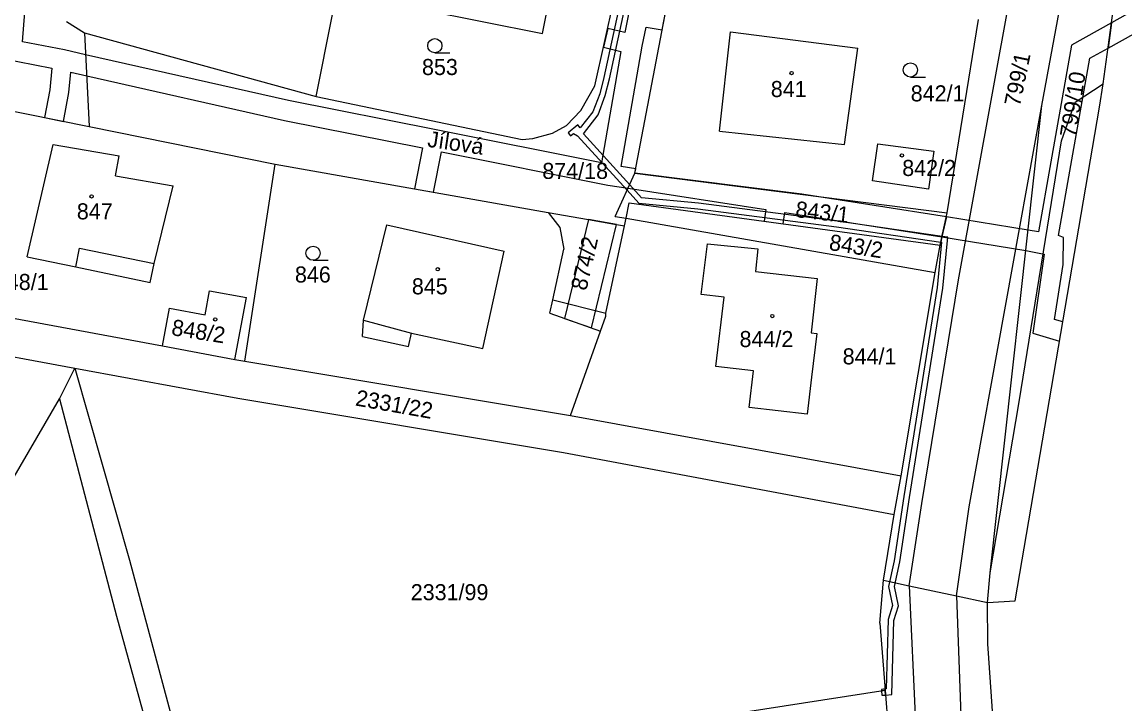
# Model space of a CAD drawing. Extents: x -785744 to -782822, y -1067550 to -1063910.
# Drawn here: x -783511.1 to -783394.4, y -1066451.8 to -1066379.6 of the extents above; entities that cross this region are included whole.
import ezdxf

# ---------------------------------------------------------------- set-up
doc = ezdxf.new("R2010")
doc.units = 0
for name, color, linetype in [('Hranice kat_území', 7, 'Continuous'), ('Hranice parcel', 7, 'Continuous'), ('Parcelní čísla', 7, 'Continuous'), ('Pop_ČP_popisy', 7, 'Continuous'), ('Vnitřní kresba', 7, 'Continuous'), ('Věcná břemena k části', 7, 'Continuous'), ('Značky budov', 7, 'Continuous'), ('Značky kultur', 7, 'Continuous')]:
    doc.layers.add(name, color=color, linetype=linetype)

msp = doc.modelspace()

# ---------------------------------------------------------------- linework, layer by layer
at = {"layer": 'Hranice kat_území'}
msp.add_lwpolyline([(-783403.72, -1066520.48), (-783408.95, -1066445.43), (-783408.98, -1066441.05), (-783406.06, -1066440.89), (-783397.12, -1066388.66), (-783396.74, -1066386.18), (-783395.27, -1066375.27), (-783394.46, -1066371.28), (-783389.04, -1066341.47), (-783386.35, -1066325.72), (-783383.12, -1066306.7), (-783381.34, -1066290.13), (-783381.25, -1066273.33), (-783383.32, -1066256.79), (-783387.23, -1066240.6), (-783392.79, -1066224.78), (-783395.02, -1066219.44), (-783397.61, -1066215.1), (-783400.51, -1066209.79), (-783408.68, -1066195.43), (-783410.8, -1066191.77), (-783425.61, -1066169.96)], dxfattribs=at)
at = {"layer": 'Hranice parcel'}
for p, q in [((-783421.15, -1066396.44), (-783420.59, -1066392.53)), ((-783420.59, -1066392.53), (-783414.67, -1066393.3)), ((-783414.67, -1066393.3), (-783415.23, -1066397.32)), ((-783415.23, -1066397.32), (-783421.15, -1066396.44)), ((-783439.26, -1066408.46), (-783438.61, -1066403.11)), ((-783438.61, -1066403.11), (-783433.28, -1066403.63)), ((-783433.28, -1066403.63), (-783433.51, -1066406.05)), ((-783433.51, -1066406.05), (-783426.98, -1066406.79)), ((-783426.98, -1066406.79), (-783427.64, -1066412.53)), ((-783436.84, -1066408.75), (-783439.26, -1066408.46)), ((-783437.72, -1066416.08), (-783436.84, -1066408.75)), ((-783427.64, -1066412.53), (-783427.04, -1066412.6)), ((-783427.04, -1066412.6), (-783427.6, -1066417.21)), ((-783433.72, -1066416.53), (-783437.72, -1066416.08)), ((-783434.18, -1066420.43), (-783433.72, -1066416.53)), ((-783427.6, -1066417.21), (-783428.07, -1066421.14)), ((-783428.07, -1066421.14), (-783434.18, -1066420.43)), ((-783419.8, -1066450.34), (-783417.13, -1066483.64))]:
    msp.add_line(p, q, dxfattribs=at)
for points in [[(-783479.98, -1066387.52), (-783474.96, -1066362.18)], [(-783450.5, -1066386.4), (-783446.43, -1066368.03)], [(-783456.04, -1066380.85), (-783454.01, -1066370.67)], [(-783403.23, -1066388.47), (-783399.85, -1066370.15)], [(-783446.27, -1066395.62), (-783442.38, -1066375.11)], [(-783468.8, -1066378.32), (-783456.04, -1066380.85)], [(-783506.41, -1066379.57), (-783504.5, -1066380.8)], [(-783413.23, -1066399.84), (-783409.94, -1066379.38)], [(-783504.5, -1066380.8), (-783479.98, -1066387.52)], [(-783504.5, -1066380.8), (-783504, -1066390.7)], [(-783437.34, -1066391.2), (-783436.16, -1066380.69)], [(-783436.16, -1066380.69), (-783422.69, -1066382.39)], [(-783424.12, -1066392.61), (-783422.69, -1066382.39)], [(-783452, -1066389), (-783450.5, -1066386.4)], [(-783479.98, -1066387.52), (-783458.2, -1066392.07)], [(-783408.7, -1066437.92), (-783403.23, -1066388.47)], [(-783514, -1066388.68), (-783504, -1066390.7)], [(-783453.5, -1066390.6), (-783452, -1066389)], [(-783504, -1066390.7), (-783484.34, -1066394.67)], [(-783455, -1066391.4), (-783453.5, -1066390.6)], [(-783458.2, -1066392.07), (-783457.08, -1066391.98)], [(-783457.08, -1066391.98), (-783455, -1066391.4)], [(-783437.34, -1066391.2), (-783424.12, -1066392.61)], [(-783510.56, -1066404.48), (-783507.82, -1066392.6)], [(-783507.82, -1066392.6), (-783500.84, -1066393.78)], [(-783501.21, -1066395.92), (-783500.84, -1066393.78)], [(-783487.55, -1066415.52), (-783484.34, -1066394.67)], [(-783484.34, -1066394.67), (-783455.44, -1066399.78)], [(-783501.21, -1066395.92), (-783495.12, -1066396.96)], [(-783448.36, -1066400.2), (-783446.27, -1066395.62)], [(-783446.27, -1066395.62), (-783413.23, -1066399.84)], [(-783497.13, -1066405.2), (-783495.12, -1066396.96)], [(-783447.21, -1066400.4), (-783446.87, -1066398.76)], [(-783446.87, -1066398.76), (-783414, -1066403.25)], [(-783455.44, -1066399.78), (-783451.19, -1066400.53)], [(-783455.44, -1066399.78), (-783454.22, -1066401.37)], [(-783414, -1066403.25), (-783413.23, -1066399.84)], [(-783474.98, -1066411.17), (-783472.52, -1066401.11)], [(-783472.52, -1066401.11), (-783460.12, -1066403.88)], [(-783451.19, -1066400.53), (-783448.44, -1066401.02)], [(-783449.34, -1066410.44), (-783447.37, -1066401.21)], [(-783448.44, -1066401.02), (-783447.37, -1066401.21)], [(-783448.36, -1066400.2), (-783447.21, -1066400.4)], [(-783447.37, -1066401.21), (-783447.21, -1066400.4)], [(-783447.21, -1066400.4), (-783414.5, -1066406.15)], [(-783454.22, -1066401.37), (-783453.81, -1066403.68)], [(-783454.96, -1066409.02), (-783453.81, -1066403.68)], [(-783414.5, -1066406.15), (-783414, -1066403.25)], [(-783510.56, -1066404.48), (-783505.43, -1066405.54)], [(-783462.37, -1066414.18), (-783460.12, -1066403.88)], [(-783505.43, -1066405.54), (-783497.55, -1066407.18)], [(-783497.55, -1066407.18), (-783497.13, -1066405.2)], [(-783418.12, -1066427.66), (-783414.5, -1066406.15)], [(-783491.74, -1066410.61), (-783491.27, -1066408.07)], [(-783491.27, -1066408.07), (-783487.38, -1066408.79)], [(-783488.6, -1066415.33), (-783487.38, -1066408.79)], [(-783455.27, -1066410.44), (-783454.96, -1066409.02)], [(-783516.62, -1066410.13), (-783496.26, -1066413.91)], [(-783496.26, -1066413.91), (-783495.52, -1066409.93)], [(-783495.52, -1066409.93), (-783491.74, -1066410.61)], [(-783455.27, -1066410.44), (-783449.92, -1066412.33)], [(-783449.37, -1066410.76), (-783449.34, -1066410.44)], [(-783475.08, -1066412.91), (-783474.98, -1066411.17)], [(-783449.92, -1066412.33), (-783449.37, -1066410.76)], [(-783475.08, -1066412.91), (-783470.23, -1066413.97)], [(-783470.23, -1066413.97), (-783469.92, -1066412.54)], [(-783469.92, -1066412.54), (-783462.37, -1066414.18)], [(-783453.1, -1066421.26), (-783449.92, -1066412.33)], [(-783517.71, -1066414), (-783505.53, -1066416.25)], [(-783496.26, -1066413.91), (-783488.6, -1066415.33)], [(-783488.6, -1066415.33), (-783487.55, -1066415.52)], [(-783507.13, -1066419.49), (-783505.53, -1066416.25)], [(-783505.53, -1066416.25), (-783488.27, -1066419.45)], [(-783505.53, -1066416.25), (-783499.73, -1066436.56)], [(-783487.55, -1066415.52), (-783453.1, -1066421.26)], [(-783512.83, -1066429.26), (-783507.13, -1066419.49)], [(-783507.13, -1066419.49), (-783501.13, -1066442.51)], [(-783488.27, -1066419.45), (-783453.83, -1066425.19)], [(-783453.1, -1066421.26), (-783418.12, -1066427.66)], [(-783453.83, -1066425.19), (-783418.86, -1066431.73)], [(-783418.86, -1066431.73), (-783418.12, -1066427.66)], [(-783419.98, -1066438.7), (-783418.86, -1066431.73)], [(-783499.73, -1066436.56), (-783493.02, -1066461.69)], [(-783408.98, -1066441.05), (-783408.7, -1066437.92)], [(-783420.37, -1066443.25), (-783419.98, -1066438.7)], [(-783501.13, -1066442.51), (-783485.11, -1066500.58)], [(-783420.37, -1066443.25), (-783419.8, -1066450.34)], [(-783493.02, -1066461.69), (-783419.8, -1066450.34)]]:
    msp.add_lwpolyline(points, dxfattribs=at)
at = {"layer": 'Vnitřní kresba'}
for points in [[(-783412.06, -1066406.93), (-783406.59, -1066376.88)], [(-783399.72, -1066388.11), (-783396.74, -1066386.18)], [(-783410.91, -1066430.94), (-783403.23, -1066388.47)], [(-783401.15, -1066392.21), (-783399.72, -1066388.11)], [(-783405.64, -1066419.83), (-783401.15, -1066392.21)], [(-783505.43, -1066405.54), (-783505.02, -1066403.56)], [(-783505.02, -1066403.56), (-783497.13, -1066405.2)], [(-783415.91, -1066430.57), (-783412.06, -1066406.93)], [(-783454.96, -1066409.02), (-783449.34, -1066410.44)], [(-783474.98, -1066411.17), (-783469.92, -1066412.54)], [(-783408.7, -1066437.92), (-783405.64, -1066419.83)], [(-783417.28, -1066439.28), (-783415.91, -1066430.57)], [(-783412.25, -1066440.35), (-783410.91, -1066430.94)], [(-783419.98, -1066438.7), (-783417.28, -1066439.28)], [(-783417.28, -1066439.28), (-783416.6, -1066453.75)], [(-783417.28, -1066439.28), (-783412.25, -1066440.35)], [(-783412.25, -1066440.35), (-783408.98, -1066441.05)], [(-783412.25, -1066440.35), (-783411.29, -1066466.61)]]:
    msp.add_lwpolyline(points, dxfattribs=at)
at = {"layer": 'Věcná břemena k části'}
for points in [[(-783445.78, -1066368.09), (-783449.55, -1066385.52)], [(-783448.97, -1066385.66), (-783445.24, -1066368.39)], [(-783511.05, -1066381.73), (-783510.15, -1066370.05)], [(-783381.57, -1066371.7), (-783395.87, -1066379.72)], [(-783396.23, -1066382.39), (-783381.37, -1066374.07)], [(-783446.94, -1066378.8), (-783447.36, -1066380.76)], [(-783443.4, -1066380.47), (-783443.02, -1066378.47)], [(-783449.15, -1066380.32), (-783449.59, -1066382.31)], [(-783447.36, -1066380.76), (-783449.15, -1066380.32)], [(-783445.5, -1066382.21), (-783445.07, -1066380.19)], [(-783445.07, -1066380.19), (-783443.4, -1066380.47)], [(-783395.87, -1066379.72), (-783400.08, -1066382.08)], [(-783395.87, -1066379.72), (-783396.23, -1066382.39)], [(-783506.62, -1066382.59), (-783511.05, -1066381.73)], [(-783504.38, -1066383.1), (-783506.62, -1066382.59)], [(-783449.59, -1066382.31), (-783447.75, -1066382.76)], [(-783447.73, -1066394.92), (-783445.5, -1066382.21)], [(-783400.08, -1066382.08), (-783402.29, -1066394.43)], [(-783398.14, -1066383.46), (-783396.23, -1066382.39)], [(-783513.35, -1066383.48), (-783507.95, -1066384.53)], [(-783482.92, -1066387.95), (-783504.38, -1066383.1)], [(-783447.75, -1066382.76), (-783449.82, -1066394.55)], [(-783400.17, -1066394.81), (-783398.14, -1066383.46)], [(-783507.95, -1066384.53), (-783508.18, -1066386.83)], [(-783506.16, -1066387.11), (-783505.94, -1066384.96)], [(-783505.94, -1066384.96), (-783504.27, -1066385.34)], [(-783504.27, -1066385.34), (-783483.36, -1066390.07)], [(-783449.55, -1066385.52), (-783449.99, -1066387.23)], [(-783449.41, -1066387.41), (-783448.97, -1066385.66)], [(-783508.18, -1066386.83), (-783508.72, -1066389.75)], [(-783506.72, -1066390.15), (-783506.16, -1066387.11)], [(-783449.99, -1066387.23), (-783450.72, -1066389.16)], [(-783467.31, -1066391.04), (-783482.92, -1066387.95)], [(-783450.18, -1066389.46), (-783449.41, -1066387.41)], [(-783450.72, -1066389.16), (-783452.06, -1066390.84)], [(-783451.73, -1066391.48), (-783450.18, -1066389.46)], [(-783508.72, -1066389.75), (-783506.72, -1066390.15)], [(-783483.36, -1066390.07), (-783468.73, -1066392.96)], [(-783452.31, -1066390.53), (-783453.35, -1066391.38)], [(-783452.06, -1066390.84), (-783452.31, -1066390.53)], [(-783449.82, -1066394.55), (-783467.31, -1066391.04)], [(-783453.35, -1066391.38), (-783453.1, -1066391.69)], [(-783453.1, -1066391.69), (-783452.78, -1066391.43)], [(-783452.78, -1066391.43), (-783452.36, -1066391.68)], [(-783452.36, -1066391.68), (-783447.1, -1066397.44)], [(-783446.83, -1066396.85), (-783451.73, -1066391.48)], [(-783468.73, -1066392.96), (-783469.59, -1066397.28)], [(-783467.58, -1066397.63), (-783466.73, -1066393.36)], [(-783466.73, -1066393.36), (-783449.14, -1066396.89)], [(-783446.18, -1066395.16), (-783447.73, -1066394.92)], [(-783446.27, -1066395.62), (-783446.18, -1066395.16)], [(-783402.29, -1066394.43), (-783403.59, -1066401.85)], [(-783401.47, -1066402.24), (-783400.17, -1066394.81)], [(-783428.62, -1066397.87), (-783446.27, -1066395.62)], [(-783469.59, -1066397.28), (-783467.58, -1066397.63)], [(-783449.14, -1066396.89), (-783447, -1066397.22)], [(-783447.1, -1066397.44), (-783445.85, -1066398.81)], [(-783447, -1066397.22), (-783432.44, -1066399.47)], [(-783445.57, -1066398.23), (-783446.83, -1066396.85)], [(-783445.85, -1066398.81), (-783439.62, -1066399.42)], [(-783439.56, -1066398.82), (-783445.57, -1066398.23)], [(-783424.88, -1066400.72), (-783439.56, -1066398.82)], [(-783413.32, -1066400.26), (-783428.62, -1066397.87)], [(-783439.62, -1066399.42), (-783424.96, -1066401.32)], [(-783432.44, -1066399.47), (-783432.6, -1066400.71)], [(-783430.58, -1066400.99), (-783430.43, -1066399.78)], [(-783430.43, -1066399.78), (-783413.8, -1066402.37)], [(-783451.19, -1066400.53), (-783453.71, -1066410.99)], [(-783448.23, -1066401.05), (-783451.19, -1066400.53)], [(-783450.87, -1066412), (-783448.23, -1066401.05)], [(-783432.6, -1066400.71), (-783430.58, -1066400.99)], [(-783424.96, -1066401.32), (-783413.92, -1066402.92)], [(-783413.79, -1066402.32), (-783424.88, -1066400.72)], [(-783413.8, -1066402.37), (-783413.32, -1066400.26)], [(-783413.32, -1066400.26), (-783413.8, -1066402.37)], [(-783404.69, -1066401.66), (-783413.32, -1066400.26)], [(-783413.92, -1066402.92), (-783413.79, -1066402.32)], [(-783413.8, -1066402.37), (-783413.92, -1066402.92)], [(-783413.79, -1066402.32), (-783413.8, -1066402.37)], [(-783413.8, -1066402.37), (-783404.93, -1066403.81)], [(-783413.17, -1066402.41), (-783413.79, -1066402.32)], [(-783413.7, -1066407.79), (-783413.17, -1066402.41)], [(-783403.59, -1066401.85), (-783404.69, -1066401.66)], [(-783400.93, -1066402.44), (-783401.47, -1066402.24)], [(-783400.96, -1066405.3), (-783400.93, -1066402.44)], [(-783413.83, -1066402.93), (-783414.3, -1066407.71)], [(-783413.92, -1066402.92), (-783413.83, -1066402.93)], [(-783404.93, -1066403.81), (-783402.99, -1066404.19)], [(-783402.99, -1066404.19), (-783404.18, -1066412.57)], [(-783401.88, -1066411.11), (-783400.96, -1066405.3)], [(-783414.3, -1066407.71), (-783417.83, -1066429.83)], [(-783417.23, -1066429.93), (-783413.7, -1066407.79)], [(-783453.71, -1066410.99), (-783450.87, -1066412)], [(-783401.01, -1066411.36), (-783401.88, -1066411.11)], [(-783404.18, -1066412.57), (-783401.35, -1066413.39)], [(-783417.83, -1066429.83), (-783418.86, -1066436.64)], [(-783418.26, -1066436.74), (-783417.23, -1066429.93)], [(-783418.86, -1066436.64), (-783419.44, -1066439.35)], [(-783418.82, -1066439.35), (-783418.26, -1066436.74)], [(-783419.44, -1066439.35), (-783419.02, -1066441.35)], [(-783418.4, -1066441.39), (-783418.82, -1066439.35)], [(-783419.02, -1066441.35), (-783419.49, -1066442.86)], [(-783418.89, -1066442.96), (-783418.4, -1066441.39)], [(-783419.49, -1066442.86), (-783419.69, -1066450.18)], [(-783419.11, -1066450.79), (-783418.89, -1066442.96)], [(-783419.81, -1066450.2), (-783420.2, -1066450.25)], [(-783420.2, -1066450.25), (-783420.19, -1066450.4)], [(-783420.19, -1066450.4), (-783419.8, -1066450.34)], [(-783419.8, -1066450.34), (-783420.19, -1066450.4)], [(-783419.69, -1066450.18), (-783419.81, -1066450.2)], [(-783419.8, -1066450.34), (-783419.81, -1066450.2)], [(-783419.81, -1066450.2), (-783419.8, -1066450.34)], [(-783419.8, -1066450.34), (-783419.76, -1066450.84)], [(-783419.76, -1066450.84), (-783419.8, -1066450.34)], [(-783420.19, -1066450.4), (-783420.14, -1066450.87)], [(-783420.14, -1066450.87), (-783419.76, -1066450.84)], [(-783419.76, -1066450.84), (-783419.11, -1066450.79)]]:
    msp.add_lwpolyline(points, dxfattribs=at)
at = {"layer": 'Značky budov'}
for centre in [(-783429.71, -1066385.04), (-783418.04, -1066393.76), (-783503.75, -1066398.09), (-783467.13, -1066405.79), (-783431.74, -1066410.75), (-783490.67, -1066411.1)]:
    msp.add_circle(centre, 0.175, dxfattribs=at)
at = {"layer": 'Značky kultur'}
for p, q in [((-783467.44, -1066382.9), (-783465.84, -1066382.9)), ((-783417.14, -1066385.46), (-783415.54, -1066385.46)), ((-783480.32, -1066404.85), (-783478.72, -1066404.85))]:
    msp.add_line(p, q, dxfattribs=at)
for centre in [(-783467.44, -1066382.15), (-783417.14, -1066384.71), (-783480.32, -1066404.1)]:
    msp.add_circle(centre, 0.75, dxfattribs=at)

# ---------------------------------------------------------------- texts
at = {"layer": 'Parcelní čísla'}
for s, p in [('853', (-783468.8, -1066385.25)), ('841', (-783431.9, -1066387.58)), ('842/1', (-783417.1, -1066388.04)), ('842/2', (-783418, -1066395.93)), ('874/18', (-783456.07, -1066396.24)), ('847', (-783505.31, -1066400.52)), ('846', (-783482.24, -1066407.2)), ('848/1', (-783513.98, -1066407.99)), ('845', (-783469.87, -1066408.45)), ('844/2', (-783435.21, -1066414.03)), ('844/1', (-783424.3, -1066415.86)), ('2331/99', (-783469.99, -1066440.81))]:
    msp.add_text(s, height=1.7, dxfattribs=at).set_placement(p)
for s, rotation, p in [('799/1', 78.3566, (-783405.56, -1066388.65)), ('843/1', 353.491, (-783429.36, -1066400.27)), ('874/2', 77.1523, (-783451.42, -1066408.13)), ('843/2', 350.8287, (-783425.82, -1066403.74)), ('848/2', 350.9335, (-783495.38, -1066412.75)), ('2331/22', 349.9755, (-783475.92, -1066420.2))]:
    msp.add_text(s, height=1.7, rotation=rotation, dxfattribs=at).set_placement(p)
at = {"layer": 'Pop_ČP_popisy'}
for s, rotation, p in [('799/10', 81.1086, (-783399.66, -1066391.91)), ('Jílová', 351.6245, (-783468.29, -1066392.83))]:
    msp.add_text(s, height=1.7, rotation=rotation, dxfattribs=at).set_placement(p)

doc.saveas('drawing.dxf')
